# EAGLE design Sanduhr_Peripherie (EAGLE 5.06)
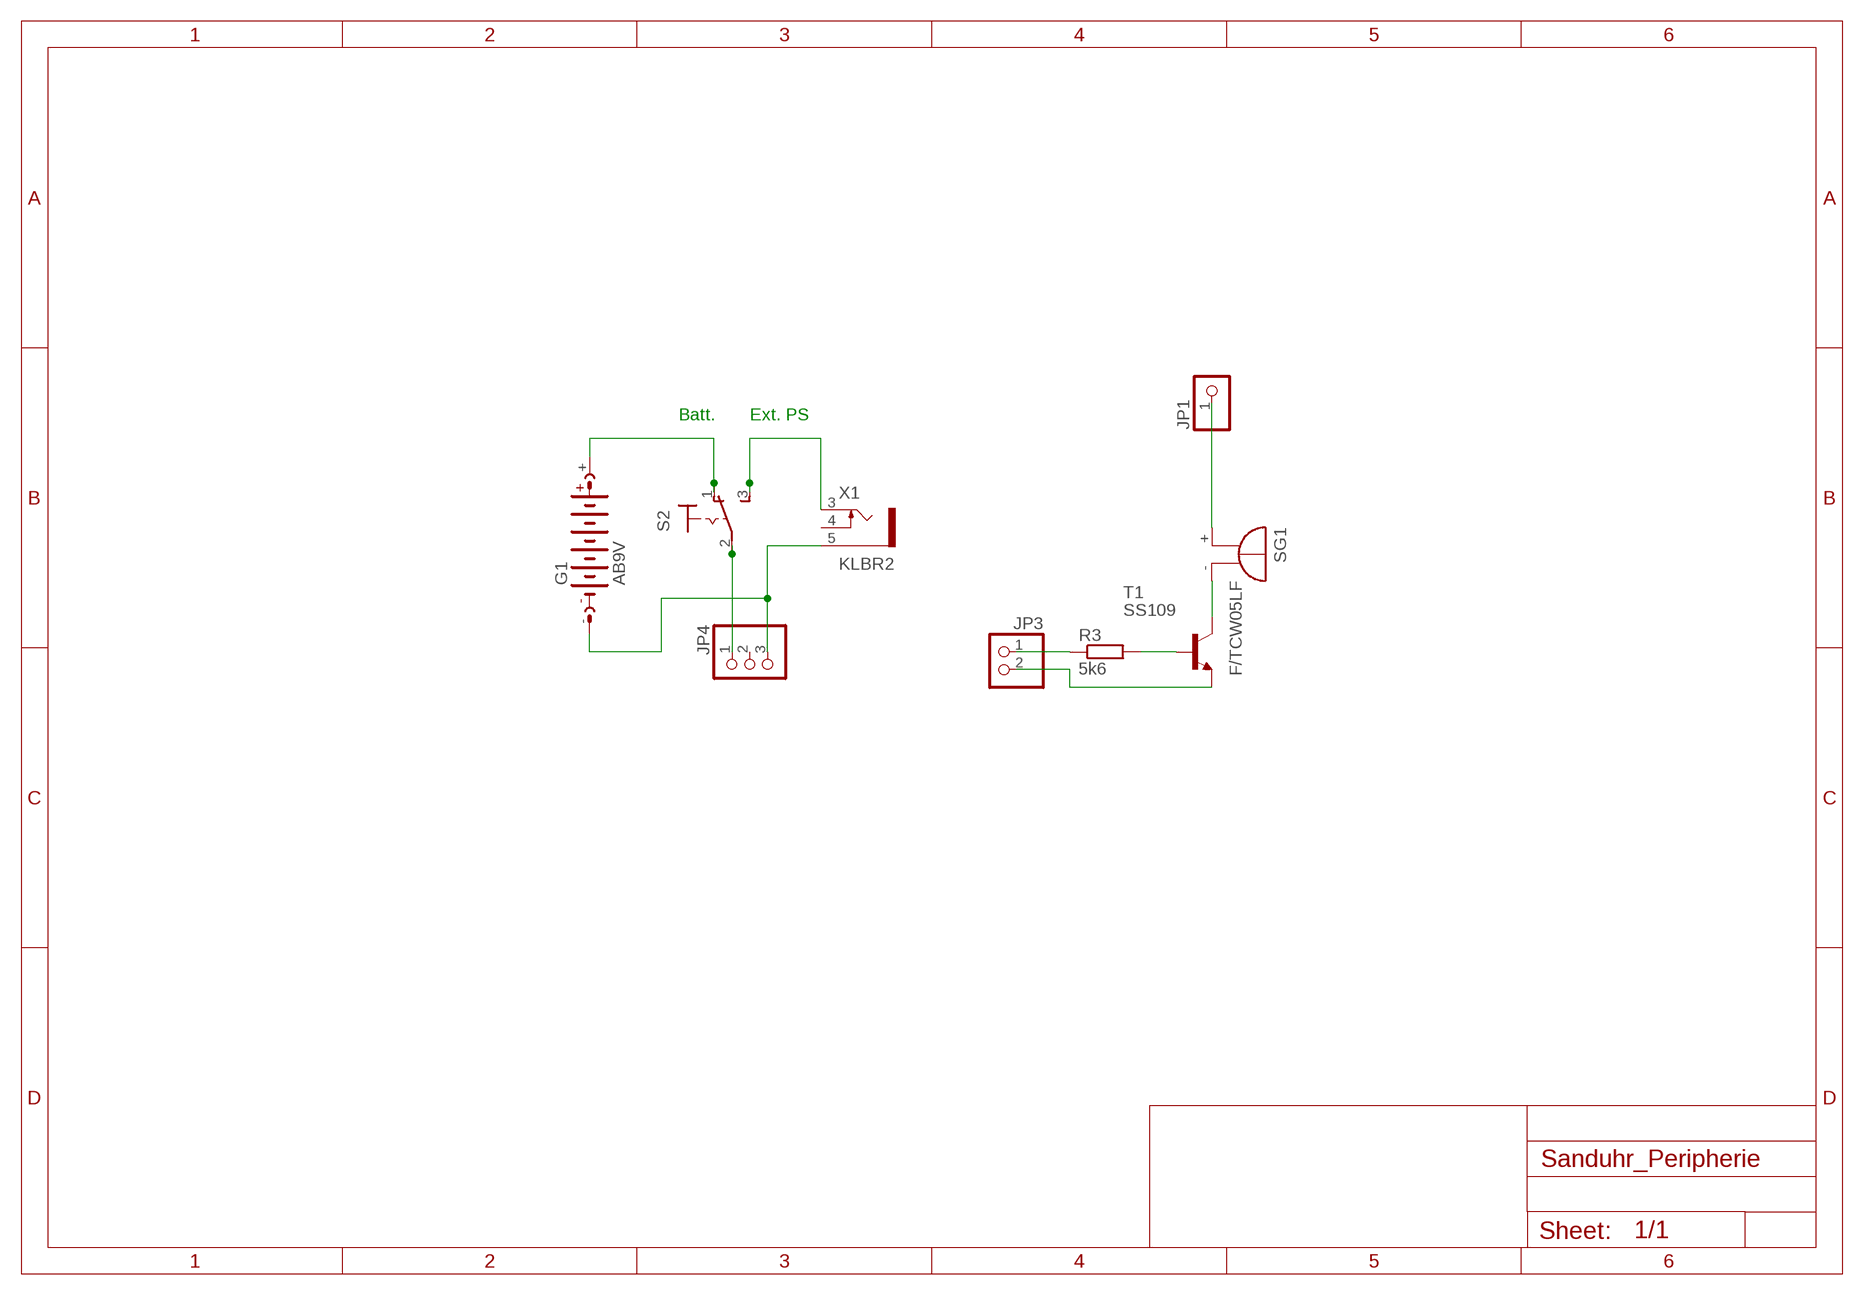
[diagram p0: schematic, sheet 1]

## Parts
G1  AB9V  [AB9V]
JP1  PINHD-1X1  [1X01]
JP3  PINHD-1X2  [1X02]
JP4  PINHD-1X3  [1X03]
R3  5k6  R-EU_0817/7V  [P0817V]
S2  M9040P  [M9040P]
SG1  F/TCW05LF  F/TMB  [F/TMB]
T1  SS109  2N706  [TO18]
X1  KLBR2  [KLBR2]

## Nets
N$1: JP1.1 SG1.+
N$2: SG1.- T1.3(C)
N$3: R3.2 T1.2(B)
N$4: JP3.1 R3.1
N$5: JP3.2 T1.1(E)
N$7: JP4.1 S2.2(P)
N$8: G1.+ S2.1(O)
N$9: S2.3(S) X1.3
N$10: G1.- JP4.3 X1.5
Unconnected: JP4.2 X1.4

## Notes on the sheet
- Batt. | Ext. PS

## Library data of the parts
G1 = battery:AB9V: 9-V BATTERY CLIP
JP1 = pinhead:PINHD-1X1: PIN HEADER
JP3 = pinhead:PINHD-1X2: PIN HEADER
JP4 = pinhead:PINHD-1X3: PIN HEADER
R3 = resistor:R-EU_: RESISTOR, European symbol
S2 = switch:M9040P: TOGGLE SWITCH Marquardt
SG1 = buzzer:F/TMB: BUZZER
T1 = transistor:2N706: NPN TRANSISTOR
X1 = con-lumberg:KLBR?: Jack connectors according to JISC 6560, 2.5mm / 3.5 mm Klinkensteckverbinder nach JISC 6560, 2.5mm / 3,5 mm Source: http://www.lumberg.com/Produkte/PDFs/KLBR2.pdf www.lumberg.com/Produkte/PDFs/KLBR1.pdf

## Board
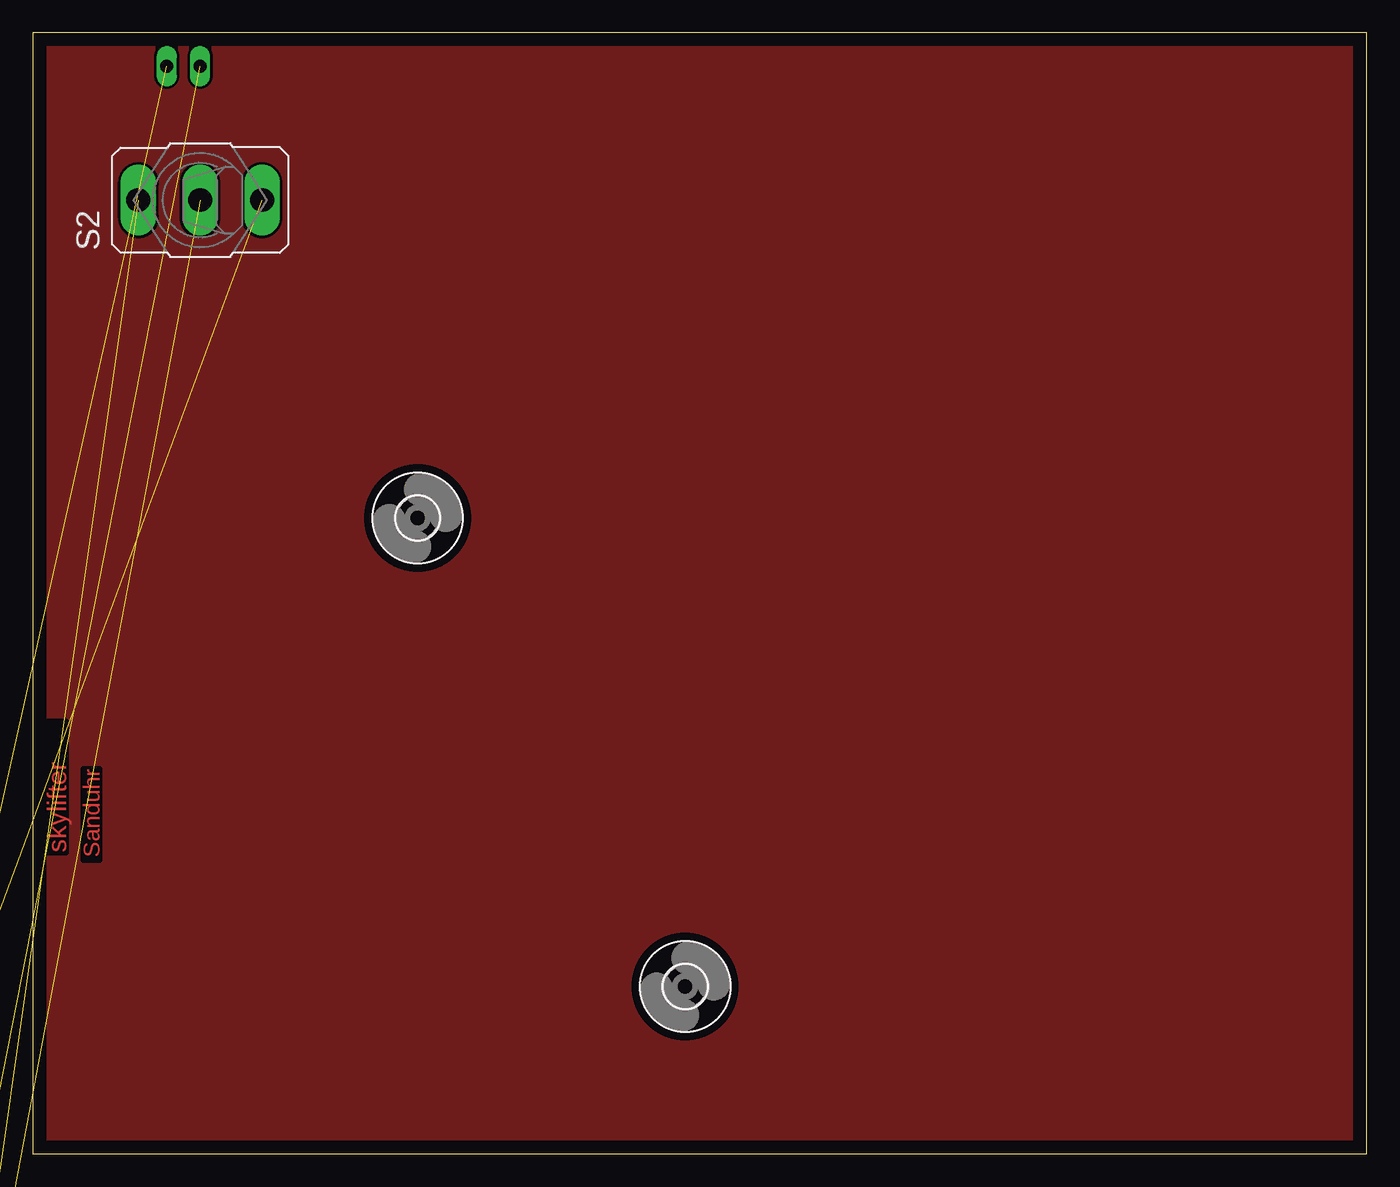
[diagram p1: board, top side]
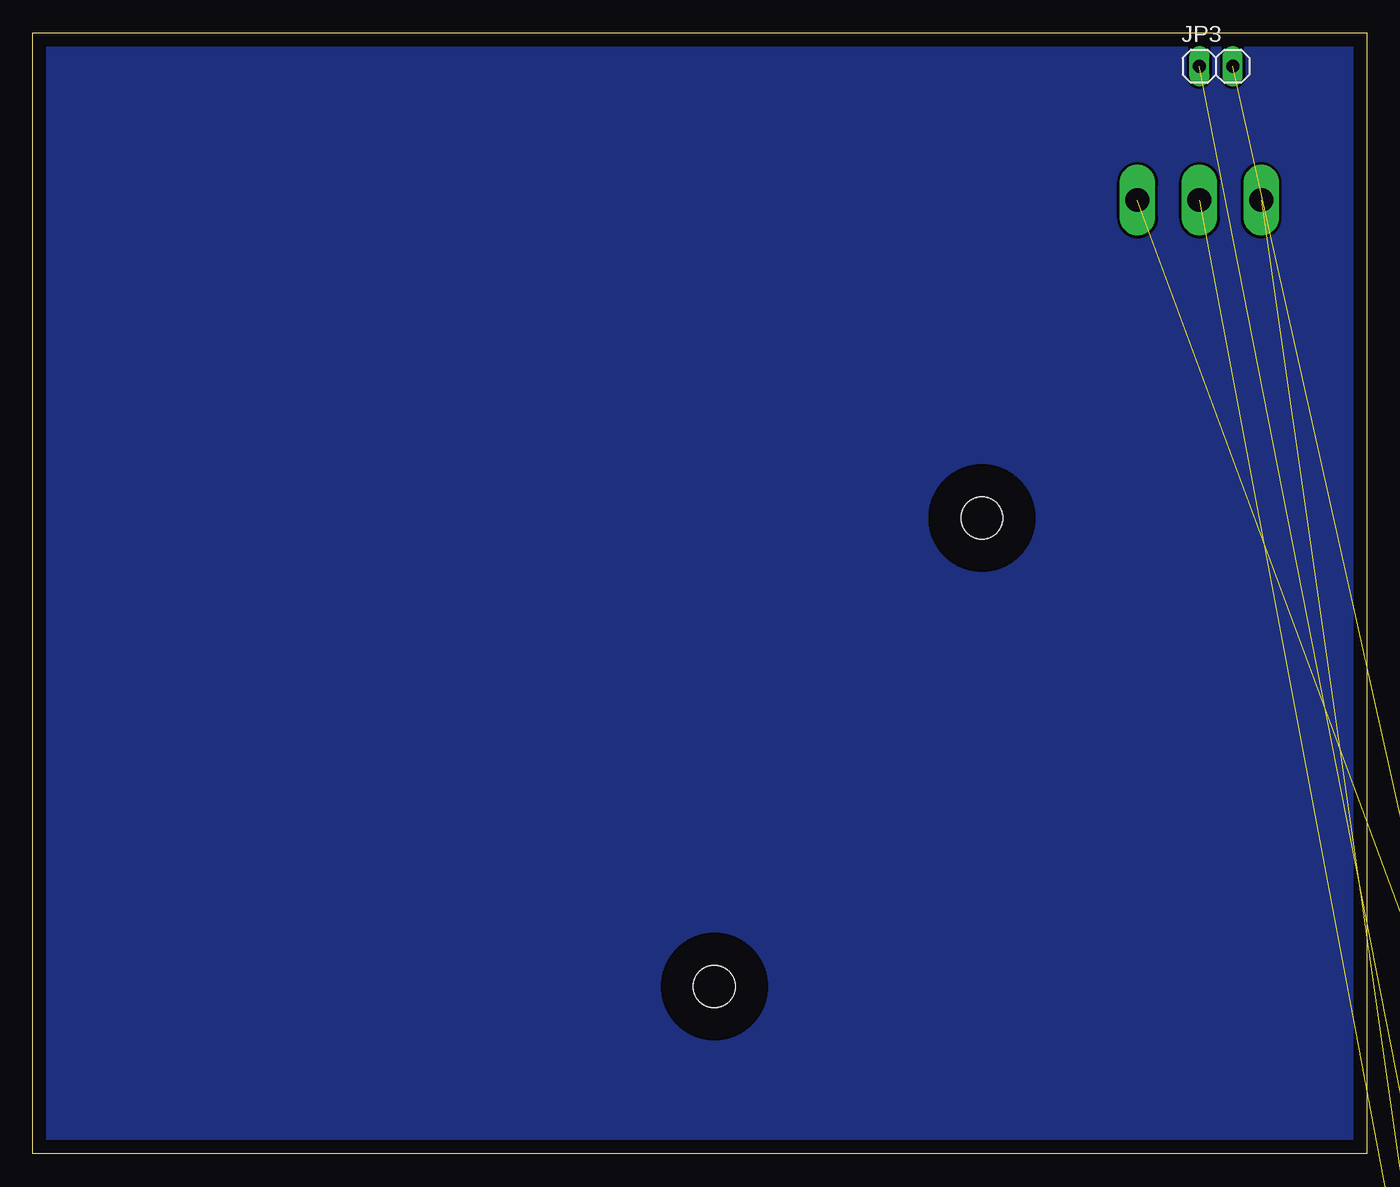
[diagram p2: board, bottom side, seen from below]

Size 101.27 x 85.08 mm. Coordinates in mm from the lower left corner, seen from the top.
Outline: 0,0 101.27,0 101.27,85.08 0,85.08 0,0
Copper layers (1*16): Top 0.035mm / dielectric 1.5mm / Bottom 0.035mm
Design rules "default": minimum track width 10mil, minimum drill 24mil, track to track 8mil, track to pad 8mil, pad to pad 8mil, via to via 8mil, smd to smd 8mil, copper to edge 40mil, drill to drill 8mil, minimum pad ring 10mil, minimum via ring 8mil, stop-mask expansion 4mil, vias tented up to drill 0mil, thermal gap 10mil

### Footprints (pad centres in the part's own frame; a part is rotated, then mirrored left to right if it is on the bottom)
3,2 = hole 3.2: 0,0
AB9V = drill 1.118 pad 3.15 octagon: + 0,2.54; - 0,-2.54
1X01 = drill 1.016 octagon: 1 0,0
1X02 = drill 1.016 long: 1 -1.27,0; 2 1.27,0
1X03 = drill 1.016 long: 1 -2.54,0; 2 0,0; 3 2.54,0
P0817V = drill 1.016 octagon: 1 -5.08,0; 2 1.27,0
M9040P = drill 1.803 long: 1 0,4.699; 2 0,0; 3 0,-4.699
F/TMB = drill 1.016 pad 2.159 octagon: + 3.81,0; - -3.81,0
TO18 = drill 0.813 octagon: 1 -1.27,-1.27; 2 1.27,-1.27; 3 1.27,1.27
KLBR2 = drill 1 pad 1.8 long: 3 0,-6.35; 4 -5.3,-4.35; 5 0,6.35

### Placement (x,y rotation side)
E$1  [3,2]  49.53,12.7 0 top
E$2  [3,2]  29.21,48.26 0 top
G1  not placed on the board
JP1  not placed on the board
JP3  11.43,82.55 0 bottom
JP4  not placed on the board
R3  not placed on the board
S2  12.7,72.39 90 top
SG1  not placed on the board
T1  not placed on the board
X1  not placed on the board

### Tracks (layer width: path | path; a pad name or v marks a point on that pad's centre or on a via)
GND
  pour Bottom: 0,85.09 101.6,85.09 101.6,0 0,0
N$1  (1 unrouted)
N$2  (1 unrouted)
N$3  (1 unrouted)
N$4  (1 unrouted)
N$5  (1 unrouted)
N$7  (1 unrouted)
N$8  (1 unrouted)
N$9  (1 unrouted)
N$10  (2 unrouted)
VCC
  pour Top: 0,85.09 101.6,85.09 101.6,0 0,0

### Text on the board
Top: Sanduhr | skylifter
